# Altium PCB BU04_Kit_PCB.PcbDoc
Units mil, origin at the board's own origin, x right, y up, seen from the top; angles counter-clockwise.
Board outline 2250 x 2505 mil, 2 copper layers (Top Layer, Bottom Layer); 23 components, 40 nets, 137 pads, 56 vias.
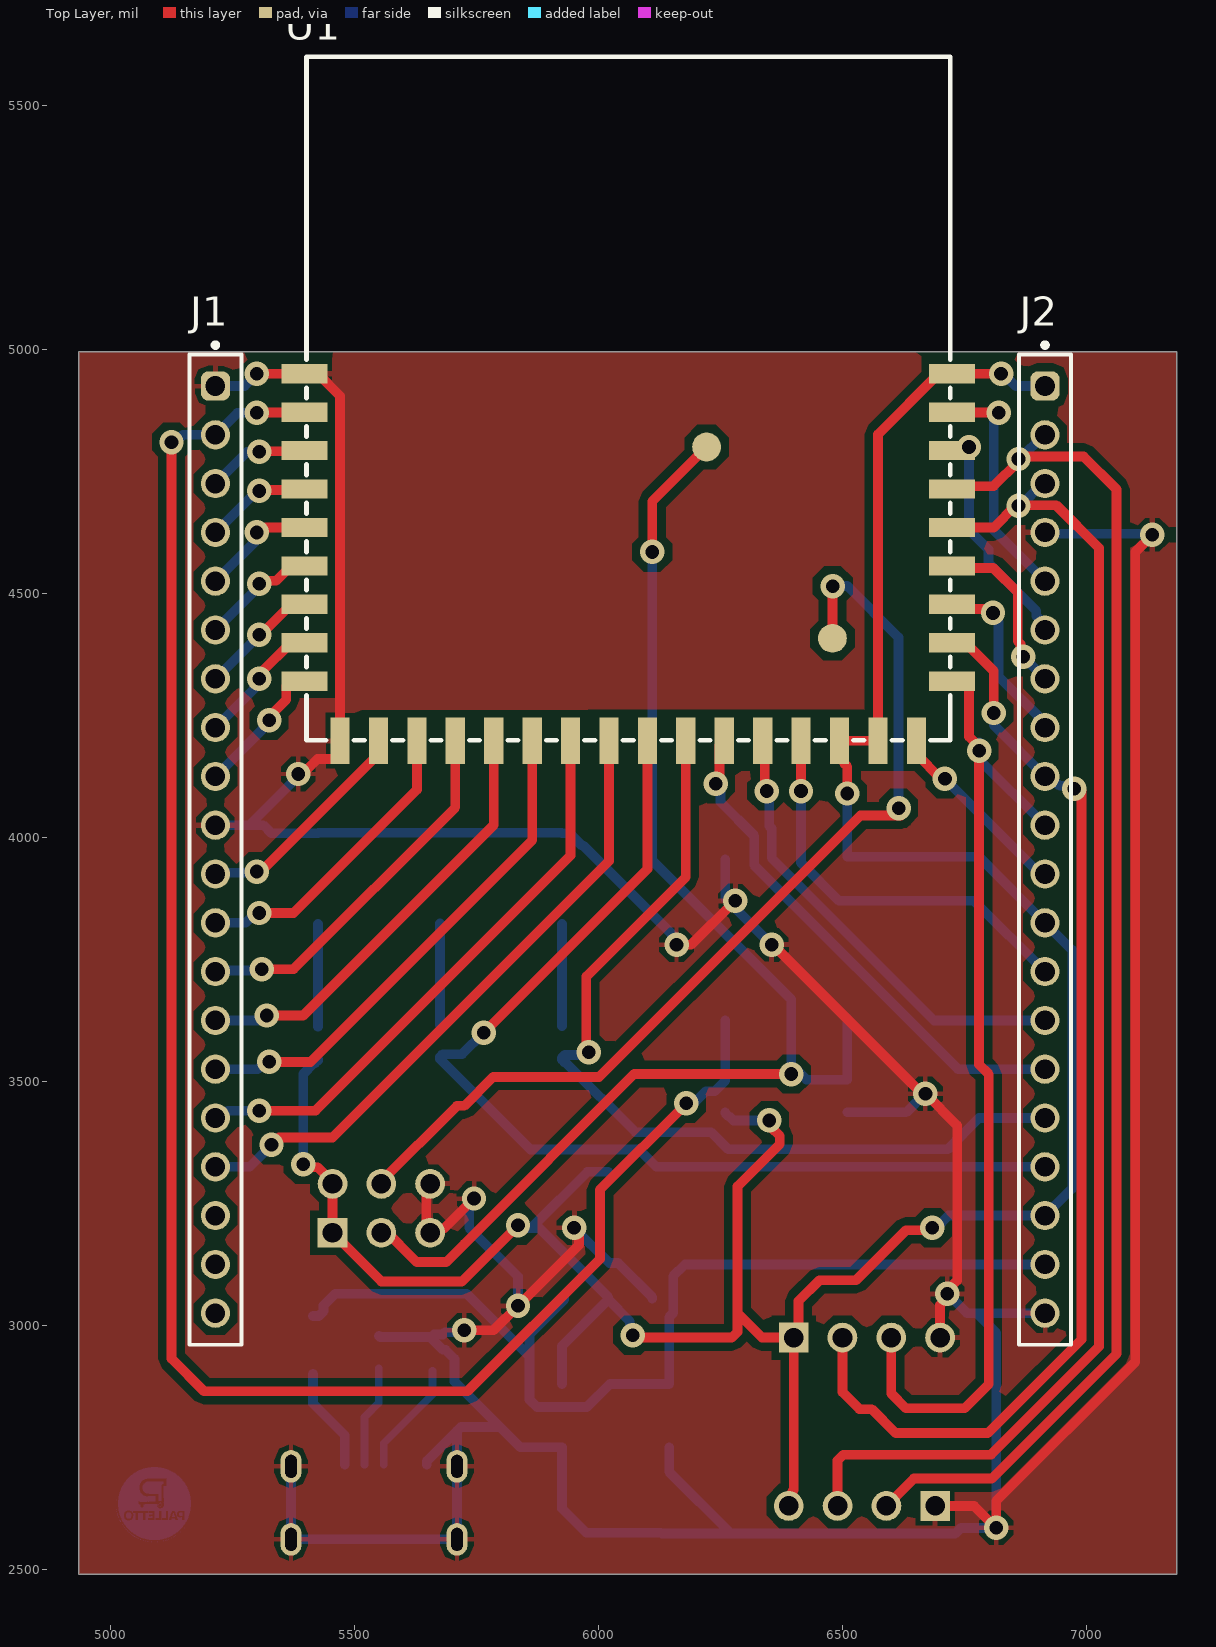
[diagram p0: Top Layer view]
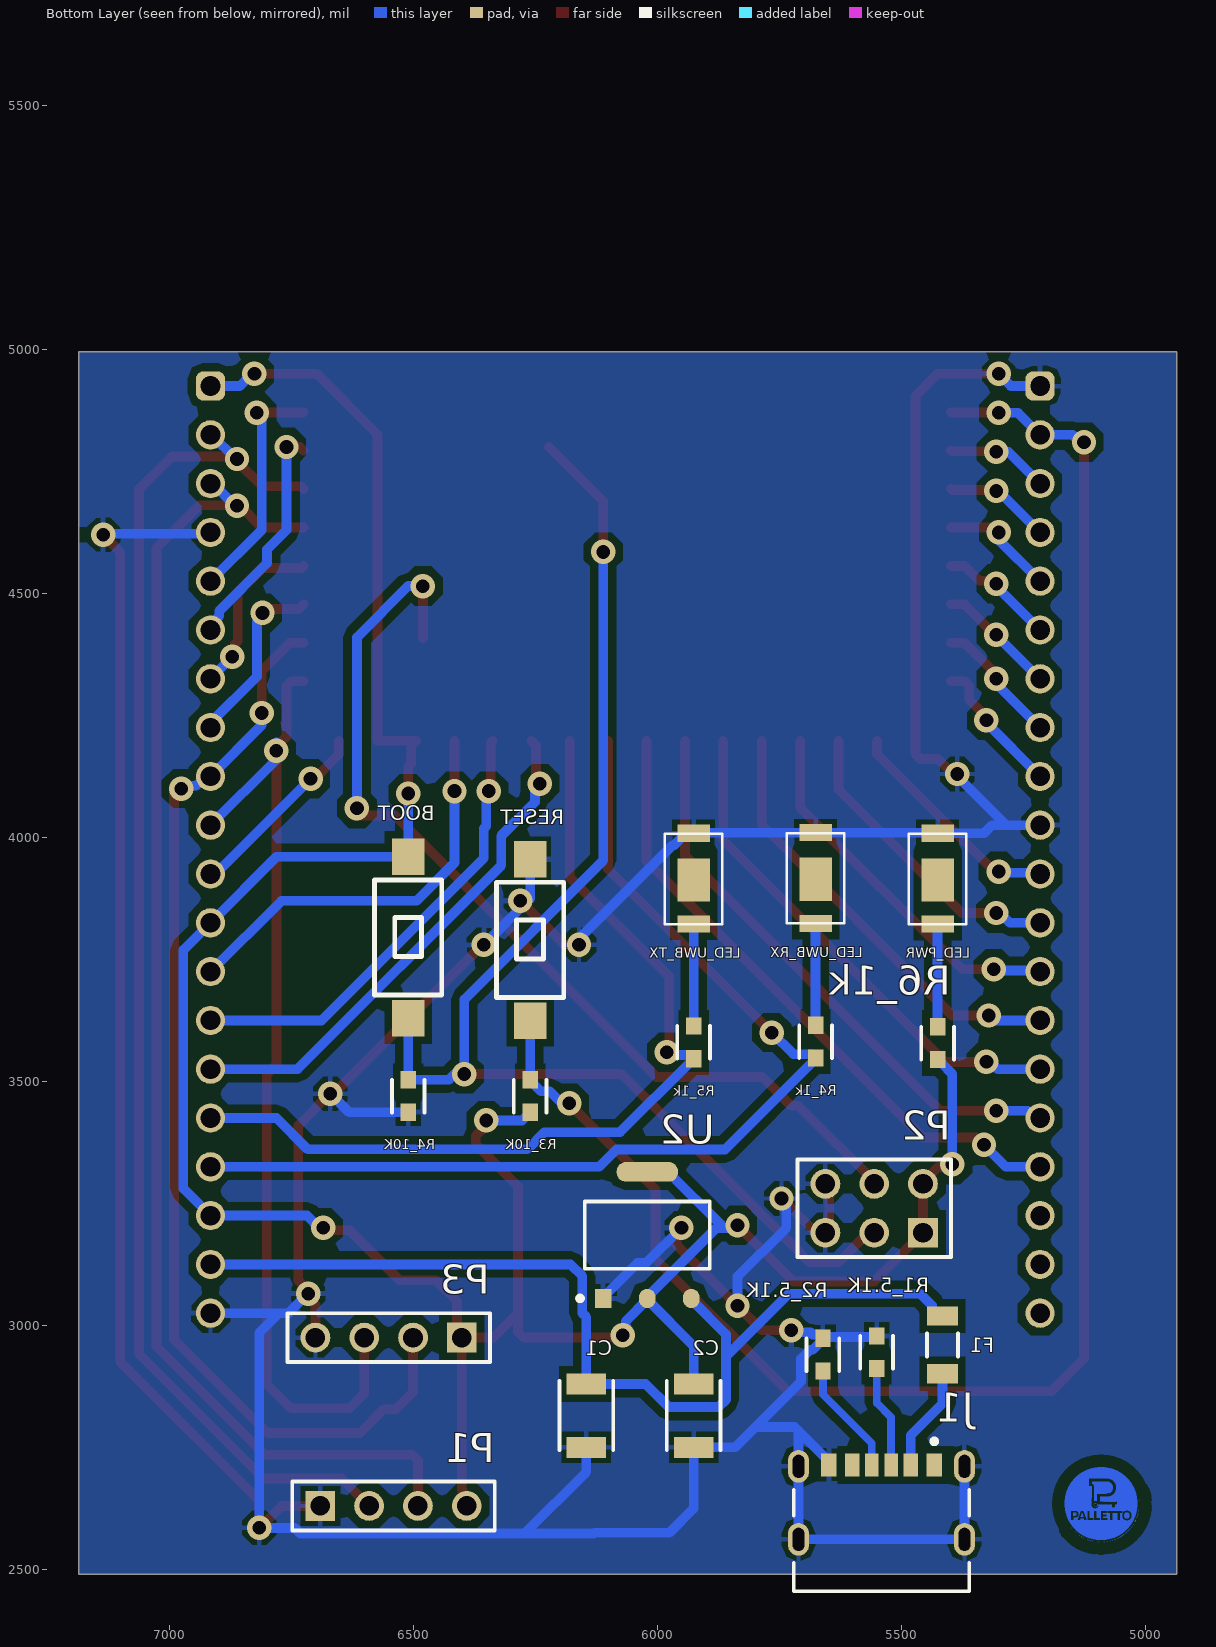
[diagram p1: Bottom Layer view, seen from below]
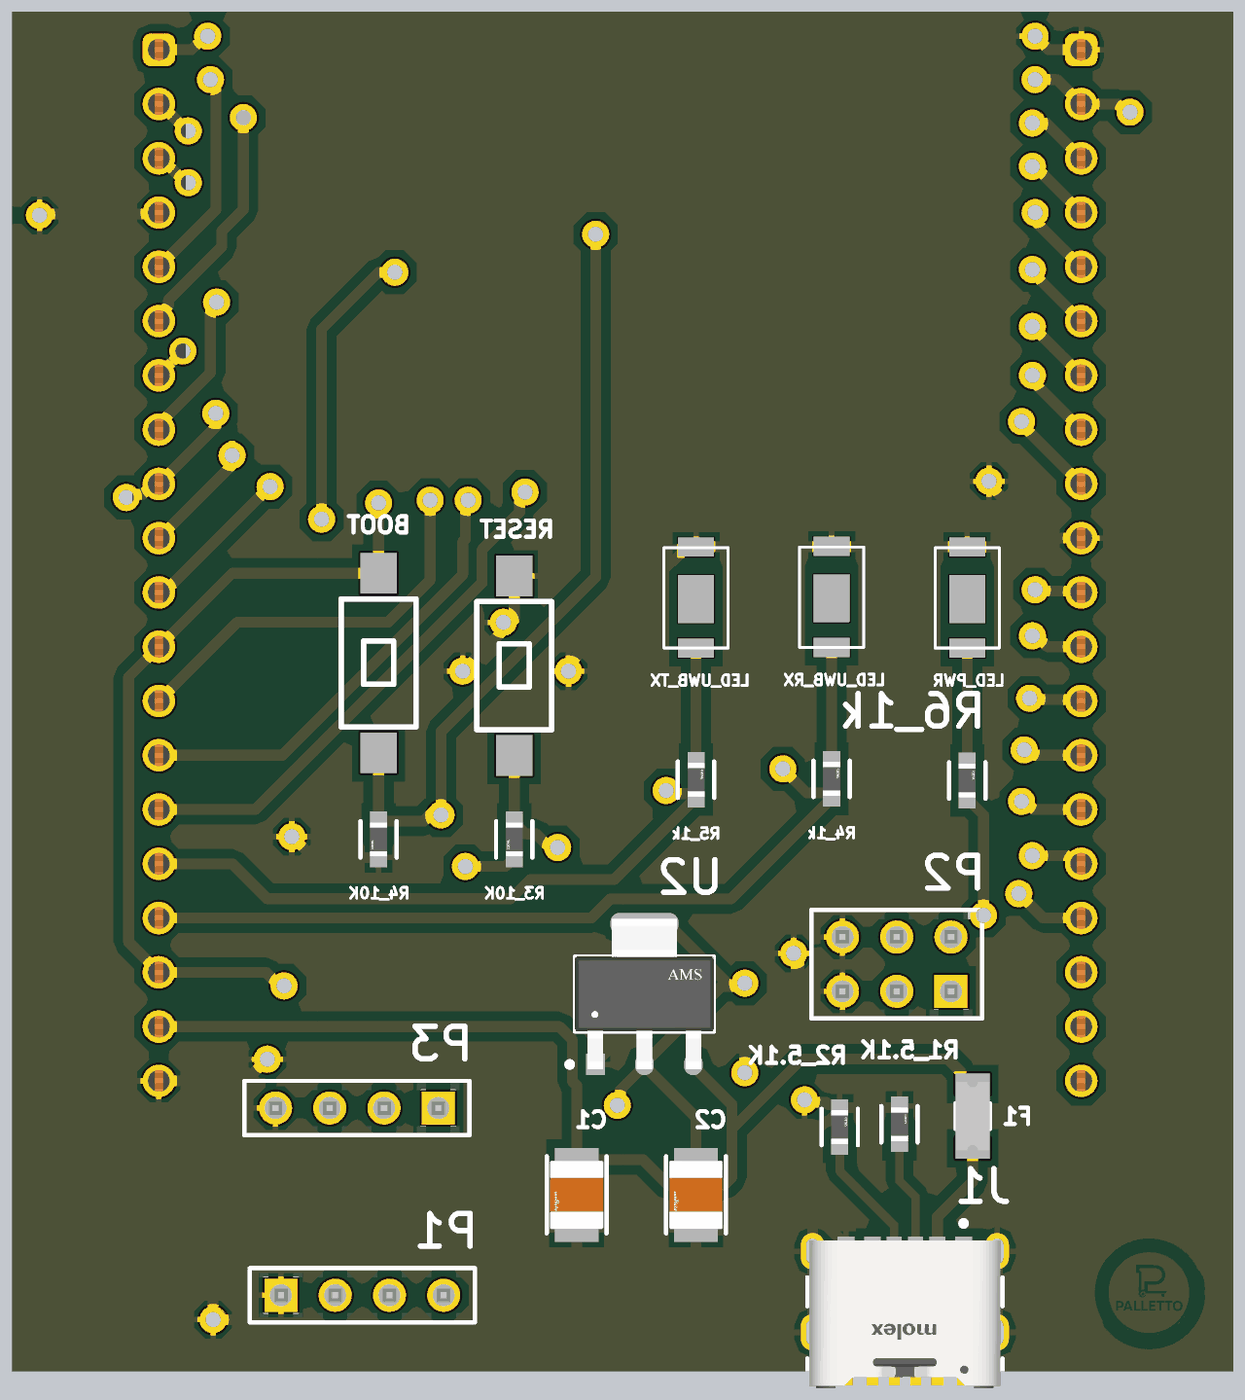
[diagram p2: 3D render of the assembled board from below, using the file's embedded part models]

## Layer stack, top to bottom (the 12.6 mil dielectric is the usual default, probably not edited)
Top Solder: solder mask 0.4, Solder Resist, Dk 3.5
Top Layer: signal copper 1.4
Dielectric 1: dielectric 12.6, FR-4, Dk 4.8
Bottom Layer: signal copper 1.4
Bottom Solder: solder mask 0.4, Solder Resist, Dk 3.5

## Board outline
4935,2490 4935,4995 7185,4995 7185,2490

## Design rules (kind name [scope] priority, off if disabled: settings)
Clearance [All] p1: gap=15.75 ignorepadtopadclearanceinfootprint=FALSE except(11.4: SMDPad-SMDPad; 23.62: Fill-Fill Fill-Poly Fill-Region Fill-Text Fill-Hole Poly-Poly Poly-Region Poly-Text Poly-Hole Region-Region Region-Text Region-Hole)
MinimumSolderMaskSliver [All] p1: minsoldermaskwidth=0.1
PolygonConnect [All] p1: connectstyle=Relief reliefconductorwidth=10 reliefentries=4 polygonreliefangle="90 Angle" airgapwidth=10
RoutingVias [All] p1: holewidth=25 width=60 viastyle="Through Hole" minholewidth=23.62 minwidth=55.12 maxholewidth=50 maxwidth=100
SilkToSilkClearance [All] p1: silktosilkclearance=0.1
SilkToSolderMaskClearance [IsPad] p1: minsilkscreentomaskgap=0 clearancetoexposedcopper=TRUE
SolderMaskExpansion [All] p1: expansion=4 istentingtop=FALSE
UnRoutedNet [All] p1: checkbadconnections=TRUE
Width [All] p1: maxlimit=118.11 minlimit=15.75 preferedwidth=20 minimp=50.000000 maximp=50.000000 favimp=50.000000
26 further rules are at their usual default settings.

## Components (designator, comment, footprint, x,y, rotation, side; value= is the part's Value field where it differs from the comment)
BOOT "SMD TACTILE SWITCH 3X6X2.5MM" SW-SMD_L6.0-W3.5-LS8.0 6510,3795 r90 bottom
C1 "GCJ32ER71E106MA18L" FP-GCJ32E-0_4-0_3-MFG 6145,2815 r270 bottom
C2 "GCJ32ER71E106MA18L" FP-GCJ32E-0_4-0_3-MFG 5925,2815 r270 bottom
F1 "MF-NSMF150-2" BOUR-MF-NSMF150-2_V 5415,2960 r90 bottom
J1 "217175-0001" FP-217175-0001-MFG 5540,2595 r0 bottom
J1 "61302011821" 61302011821 5215,3975 r270 top
J2 "61302011821" 61302011821 6915,3975 r270 top
LED_PWR "5730-LED" 5730-LED 5425,3915 r90 bottom
LED_UWB_RX "5730-LED" 5730-LED 5675,3916.3 r90 bottom
LED_UWB_TX "5730-LED" 5730-LED 5925,3915 r90 bottom
P1 "Debugger" SMTC-MTSW-104-07-X-S-170 6690,2630 r180 bottom
P2 "boot_mode" SMTC-MTSW-103-07-X-D-244 5455,3190 r0 bottom
P3 "UART1" SMTC-MTSW-104-07-X-S-170 6400,2975 r0 bottom
R1_5.1K "AF0603FR-075K1L" FP-AF0603-MFG 5550,2945 r90 bottom
R2_5.1K "AF0603FR-075K1L" FP-AF0603-MFG 5660,2940 r90 bottom
R3_10K "AF0603FR-075K1L" FP-AF0603-MFG 6260,3470 r270 bottom
R4_1k "AF0603FR-075K1L" FP-AF0603-MFG 5675,3581.54 r90 bottom
R4_10K "AF0603FR-075K1L" FP-AF0603-MFG 6510,3470 r270 bottom
R5_1k "AF0603FR-075K1L" FP-AF0603-MFG 5925,3580 r90 bottom
R6_1k "AF0603FR-075K1L" FP-AF0603-MFG 5425,3578.46 r90 bottom
RESET "SMD TACTILE SWITCH 3X6X2.5MM" SW-SMD_L6.0-W3.5-LS8.0 6260,3790 r90 bottom
U1 "BU04" WIRELM-SMD_BU04 6060.95,4574.13 r0 top
U2 "AMS1117-3.3" FP-AMS1117-IPC_C 6020,3185 r90 bottom

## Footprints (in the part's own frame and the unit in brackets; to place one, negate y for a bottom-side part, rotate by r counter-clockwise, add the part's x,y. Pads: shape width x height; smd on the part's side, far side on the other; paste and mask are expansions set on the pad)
5730-LED [mm]
  rect 0.9x1.7 smd paste+0 mask+0.051: A(-2.35,0) C(2.38,0)
  rect 2.25x1.7 smd paste+0 mask+0.051: P$2(-0.055,0)
  silkscreen extent -2.35,-1.5 2.35,1.5
61302011821 [mm] "Socket Header, Pitch 2.54 mm, THT, Vertical, single row, 20p"
  rrect50% 1.52x1.52 hole 1.02: 1(-24.13,0)
  round 1.52 hole 1.02: 2(-21.59,0) 3(-19.05,0) 4(-16.51,0) 5(-13.97,0) 6(-11.43,0) 7(-8.89,0) 8(-6.35,0) 9(-3.81,0) 10(-1.27,0) 11(1.27,0) 12(3.81,0) 13(6.35,0) 14(8.89,0) 15(11.43,0) 16(13.97,0) 17(16.51,0) 18(19.05,0) 19(21.59,0) 20(24.13,0)
  silkscreen extent -26.38,-1.35 25.78,1.35, body extent -25.65,-1.25 25.65,1.25, height 8.55
BOUR-MF-NSMF150-2_V [mm] "SMD, 2-Leads, Body 3.2x1.6mm"
  rect 1x1.6 smd: 1(-1.5,0) 2(1.5,0)
  silkscreen extent -0.6,-0.8 0.6,0.8, body extent -1.6,-0.8 1.6,0.8, height 0.55
FP-217175-0001-MFG [mm]
  rrect100% 1.1x1.7 hole 1.2 slot 0.6 at 0 deg paste-2539.97 mask+0: 1(-4.32,-2.95) 2(4.32,-2.95) 3(-4.32,0.85) 4(4.32,0.85)
  rect 0.7x1.2 smd paste+0 mask+0: A5(-0.5,-3.03) B5(0.5,-3.03)
  rect 0.76x1.2 smd paste+0 mask+0: A9(1.52,-3.03) B9(-1.52,-3.03)
  rect 0.8x1.2 smd paste+0 mask+0: A12(2.75,-3.03) B12(-2.75,-3.03)
  silkscreen extent -4.57,-4.37 4.57,3.55, body extent -4.47,-3.45 4.47,3.45, height 3.46
FP-AF0603-MFG [mm]
  rect 0.9x0.8 smd paste+0 mask+0: 1(-0.85,0) 2(0.85,0)
  silkscreen extent -0.85,-0.85 0.85,0.85, body extent -0.8,-0.4 0.8,0.4, height 0.55
FP-AMS1117-IPC_C [mm]
  rect 1.004x0.872 smd paste+0 mask+0: 1(-3.295,2.29)
  rrect100% 1.004x0.872 smd paste+0 mask+0: 2(-3.295,0) 3(-3.295,-2.29)
  rrect87% 1.004x3.182 smd paste+0 mask+0: 4(3.295,0)
  silkscreen extent -3.42,-3.25 1.75,3.63, body extent -3.53,-3.25 3.53,3.25, height 1.8
FP-GCJ32E-0_4-0_3-MFG [mm]
  rect 1.1x2.05 smd paste+0 mask+0: 1(-1.65,0) 2(1.65,0)
  silkscreen extent -1.8,-1.4 1.8,1.4, body extent -1.6,-1.25 1.6,1.25, height 2.8
SMTC-MTSW-103-07-X-D-244 [mm] "Assembly .025\" [.64] SQ Post Terminal Strip, 2x3 Pins, Vertical, 2.54mm Pitch, Male"
  rect 1.55x1.55 hole 1.02: 1(0,0)
  round 1.55 hole 1.02: 2(0,-2.54) 3(2.54,0) 4(2.54,-2.54) 5(5.08,0) 6(5.08,-2.54)
  silkscreen extent -1.46,-3.81 6.54,1.27, body extent -1.27,-3.81 6.35,1.27, height 2.18
SMTC-MTSW-104-07-X-S-170 [mm] "Assembly .025\" [.64] SQ Post Terminal Strip, 1x4 Pins, Vertical, 2.54mm Pitch, Male"
  rect 1.55x1.55 hole 1.02: 1(0,0)
  round 1.55 hole 1.02: 2(2.54,0) 3(5.08,0) 4(7.62,0)
  silkscreen extent -1.46,-1.27 9.08,1.27, body extent -1.27,-1.27 8.89,1.27, height 4.06
SW-SMD_L6.0-W3.5-LS8.0 [mm]
  rect 1.9x1.7 smd paste+0 mask+0.102: 1(-4.2,0) 2(4.2,0)
  silkscreen extent -3,-1.75 3,1.75
WIRELM-SMD_BU04 [mm]
  rect 2.4x1 smd paste+0 mask+0.051: 1(-16.85,9.55) 2(-16.85,7.55) 3(-16.85,5.55) 4(-16.85,3.55) 5(-16.85,1.55) 6(-16.85,-0.45) 7(-16.85,-2.45) 8(-16.85,-4.45) 9(-16.85,-6.45) 26(16.85,-6.45) 27(16.85,-4.45) 28(16.85,-2.45) 29(16.85,-0.45) 30(16.85,1.55) 31(16.85,3.55) 32(16.85,5.55) 33(16.85,7.55) 34(16.85,9.55)
  rect 1x2.4 smd paste+0 mask+0.051: 10(-15,-9.55) 11(-13,-9.55) 12(-11,-9.55) 13(-9,-9.55) 14(-7,-9.55) 15(-5,-9.55) 16(-3,-9.55) 17(-1,-9.55) 18(1,-9.55) 19(3,-9.55) 20(5,-9.55) 21(7,-9.55) 22(9,-9.55) 23(11,-9.55) 24(13,-9.55) 25(15,-9.55)
  round 1.5 smd paste+0 mask+0.051: 35(4.08,5.74) 36(10.63,-4.22)
  silkscreen extent -16.75,-9.52 16.76,26.05

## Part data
BOOT RESET: Manufacturer=USAKRO, Manufacturer Part=UK-B0240-R-250
C1 C2: library part CMP-06035-029490-1, "Capacitor 10uF ±20%, X7R, 25VDC, SMD 1210 (3225 metric)"
F1: library part CMP-2000-06693-1, "PTC Resettable Fuse, 6 V, 100 A, -40 to 85 degC, 2-Pin SMD, RoHS, Tape and Reel", Current Rating=100A, Hold Current=1.5A, Manufacturer=Bourns, Maximum Voltage=6VDC, Maximum Voltage DC=6V, Operating Temperature Range=-40Cto+85C, Package / Case=1206(3216metric), Package Description="2-Pin Surface Mount Device, Body 3.2 x 1.6 mm", Resistance=130mOhms, Trip Current=3A
J1: library part CMP-04767-000026-1, "CONN RCP USB2.0 C 6+18P SMD RA"
J1 J2: library part CMP-1502-01348-4, "THT Vertical Socket Header WR-PHD, Pitch 2.54 mm, Single Row, 20 pins", Contact Resistance=20mΩ, Current Rating=3A, Operating Supply Voltage=250V
P1 P3: library part CMP-1024-00104-1, "Modified .025\" SQ Post Header, Through-hole, Vertical, -55 to 125 degC, 2.54 mm Pitch, 4-Pin, Male, RoHS", Manufacturer=Samtec, PartNumber=MTSW-104-07-G-S-170, Temperature Range="-55 to 125 degC"
P2: library part CMP-1024-00096-1, "Modified .025\" SQ Post Header, Through-hole, Vertical, -55 to 125 degC, 2.54 mm Pitch, 6-Pin, Male, RoHS", Manufacturer=Samtec, PartNumber=MTSW-103-07-G-D-244, Temperature Range="-55 to 125 degC"
R1_5.1K R2_5.1K: library part CMP-03412-041991-1, "Anti-Sulfurated Chip Resistors Automotive Grade 5.1kΩ 1% 100ppm/°C 0603", Case/Package=0603, Max Operating Temperature=155°C, Max Power Dissipation=100mW, Min Operating Temperature=-55°C, Resistance=5.1kR, Resistor Type="Thick Film", Temperature Coefficient=100ppm/°C, Tolerance=1%
R3_10K R4_10K: library part CMP-03412-041991-1, "Anti-Sulfurated Chip Resistors Automotive Grade 5.1kΩ 1% 100ppm/°C 0603", Case/Package=0603, Max Operating Temperature=155°C, Max Power Dissipation=100mW, Min Operating Temperature=-55°C, Resistance=10kR, Resistor Type="Thick Film", Temperature Coefficient=100ppm/°C, Tolerance=1%
R4_1k R5_1k R6_1k: library part CMP-03412-041991-1, "Anti-Sulfurated Chip Resistors Automotive Grade 5.1kΩ 1% 100ppm/°C 0603", Case/Package=0603, Max Operating Temperature=155°C, Max Power Dissipation=100mW, Min Operating Temperature=-55°C, Resistance=1kR, Resistor Type="Thick Film", Temperature Coefficient=100ppm/°C, Tolerance=1%
U1: JLCPCB Part Class="Extended Part", Manufacturer=Ai-Thinker(安信可)
U2: library part CMP-209535-000001-1, "LDO Voltage Regulators 1A, 3.3V", Dropout Voltage=1.1V, Manufacturer="Advanced Monolithic Systems", Max Junction Temp=+125°C, Max Power Dissipation=1.2W, Max Supply Voltage=15V, Nominal Supply Current=5mA, Output Current=1A, Output Voltage=3.3V, Package=AMS1117, Temperature="-40°C to +125°C", Temperature Range Low=-40°C

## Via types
v1: diameter 50, hole 28, Top Layer to Bottom Layer, 56 vias

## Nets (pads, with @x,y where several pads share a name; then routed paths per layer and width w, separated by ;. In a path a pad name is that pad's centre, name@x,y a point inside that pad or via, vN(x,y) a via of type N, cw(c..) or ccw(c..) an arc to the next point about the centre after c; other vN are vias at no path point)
NetBOOT_1: BOOT.1 P2.3 R4_10K.1 U1.35 | length 2712
  Top Layer w20: P2.3@5560,3197.5 5627.5,3130 5688.28,3130 5725,3166.72 5725,3166.77 6073.23,3515 v1(6395,3515) ; v1(6110,4585) 6110,4688.54 U1.35
  Bottom Layer w20: v1(6110,4585) 6110,3953.23 6395,3668.23 v1(6395,3515) ; v1@6405,3525 6426.54,3503.46 R4_10K.1 BOOT.1
NetBOOT_2: BOOT.2 C2.1 J2.1 J2.12 J2.18 P1.4 P2.1 P2.2 P3.1 R3_10K.2 R6_1k.1 U1.23 U1.24 U1.34 U2.2 U2.4 | length 6011.1
  Top Layer w20: v1(5395,3330) 5400.74,3324.26 5424.64,3324.26 5448.08,3300.81 5443.9,3301.1 P2.2 5455,3200 P2.1 5555,3090 5680.12,3090 5720,3090 v1(5835,3205) ; v1(6070,2980) 6075,2975 6273.28,2975 6285,2986.72 6285,3025 ; v1@6355,3405 6371.72,3388.28 6371.72,3371.72 6285,3285 6285,3025 ; P1.4 6397.85,2637.85 6397.85,2660.08 6400,2662.23 P3.1 ; v1(6510,4090) 6510,4145 6503.7,4151.3 6503.7,4188.47 U1.23 U1.24 6572.76,4826.1 6696.77,4950.12 U1.34 6724.39,4950.06 6824.94,4950.06 v1(6825,4950) ; v1(6684.25,3200) 6679.25,3195 6630,3195 6527.5,3092.5 6452.5,3092.5 6410,3050 6410,2985 P3.1 ; 6285,3025 6335,2975 P3.1
  Bottom Layer w20: v1(5395,3330) 5395,3515 5417.28,3537.28 5419.25,3537.28 5425,3543.03 R6_1k.1 ; v1@5840.74,3199.26 5878.62,3199.26 6020,3057.88 U2.2 U2.2@6020,3052.67 ; 5867.4,3205 5977.13,3314.72 U2.4 ; C2.1 5925,2957.67 U2.2@6020,3052.67 ; v1(6070,2980) 6064.26,2985.74 6064.26,3008.41 U2.2@6020,3052.67 ; R3_10K.2 6260,3434.57 6265.75,3428.82 6267.72,3428.82 6276.54,3420 v1(6350,3420) ; P3.1@6390,2965 P3.1 ; v1@6510,4085 BOOT.2 6779.65,3960.35 J2.12 6970.67,3769.33 6970.67,3280.67 J2.18 6717.37,3225 6692.37,3200 v1(6684.25,3200) ; v1@6835,4945 6855,4925 J2.1
NetC1_1: C1.1 F1.2 J2.19 U2.3 | length 2068.4
  Bottom Layer w20: F1.2 5426.81,3019.06 5436.49,3028.74 5436.49,3040.55 5460.94,3065 5730,3065 5858.9,2936.1 ; U2.3 5929.84,3052.67 5858.9,2981.73 5858.9,2936.1 ; J2.19 6177.28,3125 6153.07,3100.79 6153.07,3024.84 6145,3016.77 C1.1 6023.42,2879.96 5976.02,2832.56 5873.98,2832.56 5858.9,2847.64 5858.9,2936.1
NetC1_2: C1.2 C2.2 J1.1 J1.2@5710.08,2711.14 J1.3@5369.92,2561.54 J1.4@5710.08,2561.54 J1.10 J1.A12 J2.4 J2.20 LED_PWR.C LED_UWB_RX.C LED_UWB_TX.C P1.1 P2.5 P2.6 P3.4 R1_5.1K.2 R2_5.1K.2 R4_10K.2 RESET.2 U1.1 U1.10 U2.1 | length 10833.3
  Top Layer w20: v1(5300,4950) 5300.06,4950.06 5397.5,4950.06 U1.1 5425.12,4950.12 5470.55,4904.69 5470.55,4198.31 U1.10 5470.4,4170.59 5460.71,4160.91 5424.02,4160.91 5393.12,4130 v1(5385,4130) ; P2.6 5647.15,3282.15 5647.15,3197.85 P2.5 5662.85,3197.85 5682.85,3197.85 v1(5745,3260) ; v1(5725,2990) 5785,2990 v1(5835,3040) 5960,3165 v1@5960,3190 ; v1(6160,3780) 6190,3780 v1(6280,3870) ; v1(6355,3780) 6357.5,3780 6662.5,3475 v1(6670,3475) 6735,3410 6735,3091.72 v1@6721.44,3078.16 ; P1.1 6770,2630 v1(6815,2585) 6815,2640 7100,2925 7100,4585 v1(7135,4620) ; P3.4 6700,3041.88 6715,3056.88 v1(6715,3065)
  Bottom Layer w20: J1.10 5285,4025 ; J1.1@5215,4925 5275,4925 v1(5300,4950) ; J1.1@5369.92,2711.14 5369.92,2561.54 5710.08,2561.54 5710.08,2711.14 5710.08,2783.98 ; v1@5387.5,4127.5 5285,4025 ; R1_5.1K.2 5552.5,2975.96 R2_5.1K.2@5657.5,2975.96 ; J1.A12 5648.27,2722.17 5710.08,2783.98 ; v1(5725,2990) 5720.75,2985.75 5685.75,2985.75 5681.18,2981.18 5662.72,2981.18 R2_5.1K.2@5657.5,2975.96 ; v1(5745,3260) 5735,3250 5735,3200 5835,3100 v1(5835,3040) ; v1(5950,3200) 6022.38,3127.62 6040.41,3127.62 6110.16,3057.88 U2.1 ; C1.2 6145,2700 6271.26,2573.74 ; v1@6154.26,3797.74 5969.13,3982.87 5966.58,3982.87 5940.75,4008.7 LED_UWB_TX.C 5924.35,4009.35 5675.65,4009.35 LED_UWB_RX.C 5674.35,4009.35 5425.65,4009.35 LED_PWR.C 5329.48,4008.7 5313.18,4025 5285,4025 ; RESET.2 6260,3875 v1(6355,3780) ; R4_10K.2 6630.68,3436.54 6669.15,3475 v1(6670,3475) ; P1.1@6671.09,2611.09 P1.1 ; v1(6715,3065) 6755,3025 6775,3025 ; J2.20 6775,3025 ; J2.4 6917.5,4622.5 7132.5,4622.5 v1(7135,4620) ; R2_5.1K.2@5657.5,2975.96 R2_5.1K.2 5660,2971.5 5681.5,2950 5686.41,2950 5705,2931.41 5705,2885 5798.05,2791.95 ; 5710.08,2783.98 5718.05,2791.95 5798.05,2791.95 ; 5798.05,2791.95 5839.96,2750.04 C2.2 5925,2625 5975,2575 6128.74,2575 6130,2573.74 6271.26,2573.74 ; 6271.26,2573.74 6731.18,2573.74 6742.44,2585 v1(6815,2585) 6815,2985 6775,3025
NetF1_1: F1.1 J1.B9 | length 213.6
  Bottom Layer w20: F1.1 5415,2839.68 5480.16,2774.53 J1.B9
NetJ1_2: J1.2@5215,4825 R3_10K.1 RESET.1 U1.2 | length 3796.7
  Top Layer w20: v1(5125,4810) 5125,2931.72 5191.72,2865 5731.77,2865 6003.01,3136.25 6003.01,3278.01 v1(6180,3455) ; v1(5300,4870) 5300.69,4870.69 5396.87,4870.69 U1.2
  Bottom Layer w20: v1(5125,4810) 5133.12,4810 5148.12,4825 5215,4825 5260,4870 v1(5300,4870) v1@5310,4870 ; v1@6200,3460 6220,3480 6238.5,3480 6260,3501.5 R3_10K.1 RESET.1
NetJ1_3: J1.3@5215,4725 U1.3 | length 200.6
  Top Layer w20: v1(5305,4790) 5306.32,4791.32 5396.24,4791.32 U1.3
  Bottom Layer w20: J1.3@5215,4725 5280,4790 v1@5295,4790
NetJ1_4: J1.4@5215,4625 U1.4 | length 212.3
  Top Layer w20: v1(5305,4710) 5306.95,4711.95 5395.61,4711.95 U1.4
  Bottom Layer w20: J1.4@5215,4625 5295,4705 v1@5300,4705
NetJ1_5: J1.5 U1.5 | length 237
  Top Layer w20: v1(5300,4625) 5308.12,4625 5318.28,4635.16 U1.5
  Bottom Layer w20: J1.5 5300,4610 v1(5300,4625)
NetJ1_6: J1.6 U1.6 | length 239.9
  Top Layer w20: v1(5305,4520) 5310.74,4525.74 5339.32,4525.74 5370,4556.42 U1.6
  Bottom Layer w20: J1.6 5305,4515 v1(5305,4520)
NetJ1_7: J1.7 U1.7 | length 245.8
  Top Layer w20: v1(5305,4415) 5307.32,4415 5370,4477.68 U1.7
  Bottom Layer w20: J1.7 v1(5305,4415)
NetJ1_8: J1.8 U1.8 | length 275.7
  Top Layer w20: v1(5305,4325) 5310.74,4330.74 5310.74,4339.68 5370,4398.94 U1.8
  Bottom Layer w20: J1.8 5305,4315 v1(5305,4325) v1@5305,4335
NetJ1_9: J1.9 U1.9 | length 292
  Top Layer w20: v1(5325,4240) 5325,4247.15 5360.32,4282.47 5360.32,4310.51 5370,4320.2 U1.9
  Bottom Layer w20: J1.9 5325,4235 v1(5325,4240) v1@5325,4245
NetJ1_11: J1.11 U1.11 | length 463.4
  Top Layer w20: v1(5300,3930) 5308.54,3930 5549.14,4170.59 U1.11
  Bottom Layer w20: J1.11 5217.5,3927.5 5297.5,3927.5 v1(5300,3930)
NetJ1_12: J1.12 U1.12 | length 626.2
  Top Layer w20: v1(5305,3845) 5375,3845 5627.88,4097.88 U1.12
  Bottom Layer w20: J1.12 5276.88,3825 5296.88,3845 v1(5305,3845)
NetJ1_13: J1.13 U1.13 | length 767.6
  Top Layer w20: v1(5310,3730) 5375,3730 5706.62,4061.62 U1.13
  Bottom Layer w20: J1.13 5217.5,3727.5 5307.5,3727.5 v1(5310,3730)
NetJ1_14: J1.14 U1.14 | length 909
  Top Layer w20: v1(5320,3635) 5395,3635 5785.36,4025.36 U1.14
  Bottom Layer w20: J1.14 5301.88,3625 5311.88,3635 v1(5320,3635)
NetJ1_15: J1.15 U1.15 | length 1047.5
  Top Layer w20: v1(5325,3540) 5410,3540 5864.1,3994.1 U1.15
  Bottom Layer w20: J1.15 5301.88,3525 5316.88,3540 v1(5325,3540)
NetJ1_16: J1.16 U1.16 | length 1185.9
  Top Layer w20: v1(5305,3440) 5420,3440 5942.84,3962.84 U1.16
  Bottom Layer w20: J1.16 5225.78,3425 5240.78,3440 v1(5305,3440)
NetJ1_17: J1.17 U1.17 | length 1312.7
  Top Layer w20: v1(5330,3370) 5345,3385 5455,3385 6021.58,3951.58 U1.17
  Bottom Layer w20: J1.17 5285,3325 v1(5330,3370)
NetJ1_A5: J1.A5 R1_5.1K.1 | length 209.5
  Bottom Layer w15.75: J1.A5@5520.51,2714.29 5520.51,2811.63 5550,2841.12 R1_5.1K.1
NetJ1_B5: J1.B5 R2_5.1K.1 | length 233.8
  Bottom Layer w15.75: J1.B5 5559.69,2758.53 5660,2858.84 R2_5.1K.1
NetJ2_2: J2.2 P1.2 U1.31 | length 2840.4
  Top Layer w20: P1.2 6646.26,2686.26 6806.07,2686.26 7061.5,2941.69 7061.5,4713.5 6994.33,4780.67 v1@6860.75,4780.67 ; U1.31 6730.13,4719.69 6809.69,4719.69 6860.75,4770.75 v1(6860.75,4775.37)
  Bottom Layer w20: v1(6860.75,4775.37) 6863.06,4775.37 6912.69,4825 J2.2
NetJ2_3: J2.3 P1.3 U1.30 | length 2791.6
  Top Layer w20: P1.3 6490,2723.28 6501.72,2735 6804.25,2735 7025.75,2956.5 7025.75,4592.98 6938.06,4680.67 6861.42,4680.67 v1(6860.75,4680) 6855,4680 6810.16,4635.16 U1.30
  Bottom Layer w20: v1(6860.75,4680) 6865.37,4680 6910.37,4725 J2.3
NetJ2_5: J2.5 U1.33 | length 474.7
  Top Layer w20: U1.33 6725.02,4870.69 6819.31,4870.69 v1(6820,4870)
  Bottom Layer w20: v1@6810,4860 6810,4630 J2.5
NetJ2_6: J2.6 U1.32 | length 477.5
  Top Layer w20: U1.32 6731.69,4800 v1(6759.25,4800)
  Bottom Layer w20: v1(6759.25,4800) 6759.25,4630.19 6799.25,4590.19 6799.25,4562.02 6897.18,4464.1 6897.18,4453.6 6915,4435.78 J2.6
NetJ2_7: J2.7 U1.29 | length 357.6
  Top Layer w20: U1.29 6728.49,4552.25 6809.02,4552.25 6859.33,4501.94 6859.33,4401.94 6865.01,4396.26 6865.01,4375.64 v1(6870.75,4369.9)
  Bottom Layer w20: v1(6870.75,4369.9) 6870.75,4369.58 6915,4325.32 J2.7
NetJ2_8: J2.8 U1.28 | length 370.7
  Top Layer w20: U1.28 6734.02,4467.99 6792.47,4467.99 6800.46,4460 v1(6808.58,4460)
  Bottom Layer w20: v1(6808.58,4460) 6808.58,4453.31 6820,4441.89 6820,4330 6915,4235 J2.8
NetJ2_9: J2.9 P3.2 U1.27 | length 2279.2
  Top Layer w20: P3.2 6500,2863.23 6535,2828.23 6560,2828.23 6608.98,2779.25 6797.95,2779.25 6990,2971.3 v1@6990,4095 ; U1.27 6751.89,4398.94 6810,4340.83 v1(6810,4255)
  Bottom Layer w20: v1(6810,4255) 6810,4230 J2.9 6925.78,4125 6945.04,4105.74 6969.26,4105.74 v1(6975,4100)
NetJ2_10: J2.10 P3.3 U1.26 | length 2060.4
  Top Layer w20: P3.3 6600,2860 6630,2830 6750,2830 6800,2880 6800,3514.69 6780,3534.69 v1(6780,4177.5) 6780,4185.62 6759.25,4206.37 6759.25,4310.51 6749.57,4320.2 U1.26
  Bottom Layer w20: v1@6780,4195 v1(6780,4177.5) 6780,4160 J2.10
NetJ2_11: J2.11 U1.25 | length 399.9
  Top Layer w20: U1.25 6651.5,4170.59 6702.09,4120 v1(6710,4120)
  Bottom Layer w20: v1@6705,4125 v1(6710,4120) 6905,3925 J2.11
NetJ2_13: J2.13 U1.22 | length 839.7
  Top Layer w20: v1(6415,4095) 6415.14,4095.14 6415.14,4198.01 U1.22
  Bottom Layer w20: v1@6410,4090 6415,4085 6415,3948.07 6493.07,3870 6770,3870 J2.13
NetJ2_14: J2.14 U1.21 | length 938.9
  Top Layer w20: U1.21 6340.77,4193.92 6340.77,4099.23 v1(6345,4095)
  Bottom Layer w20: v1@6350,4090 6350,4023.18 6354.96,4018.22 6354.96,3957.56 6687.52,3625 J2.14
NetJ2_15: J2.15 U1.20 | length 1060.3
  Top Layer w20: v1(6240,4110) 6240,4118.12 6248.11,4126.23 6248.11,4188.47 U1.20
  Bottom Layer w20: v1@6250,4110 6250,4072.63 6319.21,4003.42 6319.21,3942.75 6736.96,3525 J2.15
NetJ2_16: J2.16 R5_1k.1 U1.19 | length 1874.1
  Top Layer w20: v1@5975,3565 5975,3715 6179.06,3919.06 U1.19
  Bottom Layer w20: v1(5980,3560) 5971.88,3560 5966.13,3554.25 5930.75,3554.25 5925,3548.5 R5_1k.1 5925,3544.57 5930.75,3538.82 5932.72,3538.82 6075.55,3395.99 6230.67,3395.99 6265.91,3360.75 6715.75,3360.75 6780,3425 J2.16
NetJ2_17: J2.17 R4_1k.1 U1.18 | length 2183.3
  Top Layer w20: v1(5765,3600) 6100.32,3935.32 U1.18
  Bottom Layer w20: v1(5765,3600) 5720.79,3555.79 5680.75,3555.79 5675,3550.04 R4_1k.1 5675,3546.1 5860.86,3360.24 6083.23,3360.24 6118.47,3325 J2.17
NetLED_PWR_A: LED_PWR.A R6_1k.2 | length 210.6
  Bottom Layer w20: R6_1k.2 LED_PWR.A
NetLED_UWB_RX_A: LED_UWB_RX.A R4_1k.2 | length 208.8
  Bottom Layer w20: R4_1k.2 LED_UWB_RX.A
NetLED_UWB_TX_A: LED_UWB_TX.A R5_1k.2 | length 209
  Bottom Layer w20: R5_1k.2 LED_UWB_TX.A
NetP2_4: P2.4 U1.36 | length 2014.9
  Top Layer w20: P2.4@5552.5,3292.5 5710,3450 5725,3450 5784.25,3509.25 6001.02,3509.25 6536.77,4045 v1@6620,4045 ; U1.36 6479.73,4408.27 6479.73,4514.73 v1(6480,4515)
  Bottom Layer w20: v1(6480,4515) 6510,4515 6615,4410 v1(6615,4060)
pads on no net: J1.18 J1.19 J1.20 J1.A9 J1.B12 LED_PWR.P$2 LED_UWB_RX.P$2 LED_UWB_TX.P$2

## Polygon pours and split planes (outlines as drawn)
NetC1_2 on Bottom Layer "NETC1_2_L02_P000" (solid, remove dead copper, pour order 0): 4935,4995 7185,4995 7185,2490 4935,2490
NetC1_2 on Top Layer "NETC1_2_L01_P002" (solid, remove dead copper, pour order 2): 4935,4995 7185,4995 7185,2490 4935,2490

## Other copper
Bottom Layer:
  drawing of 239 lines, arcs and shapes, not listed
